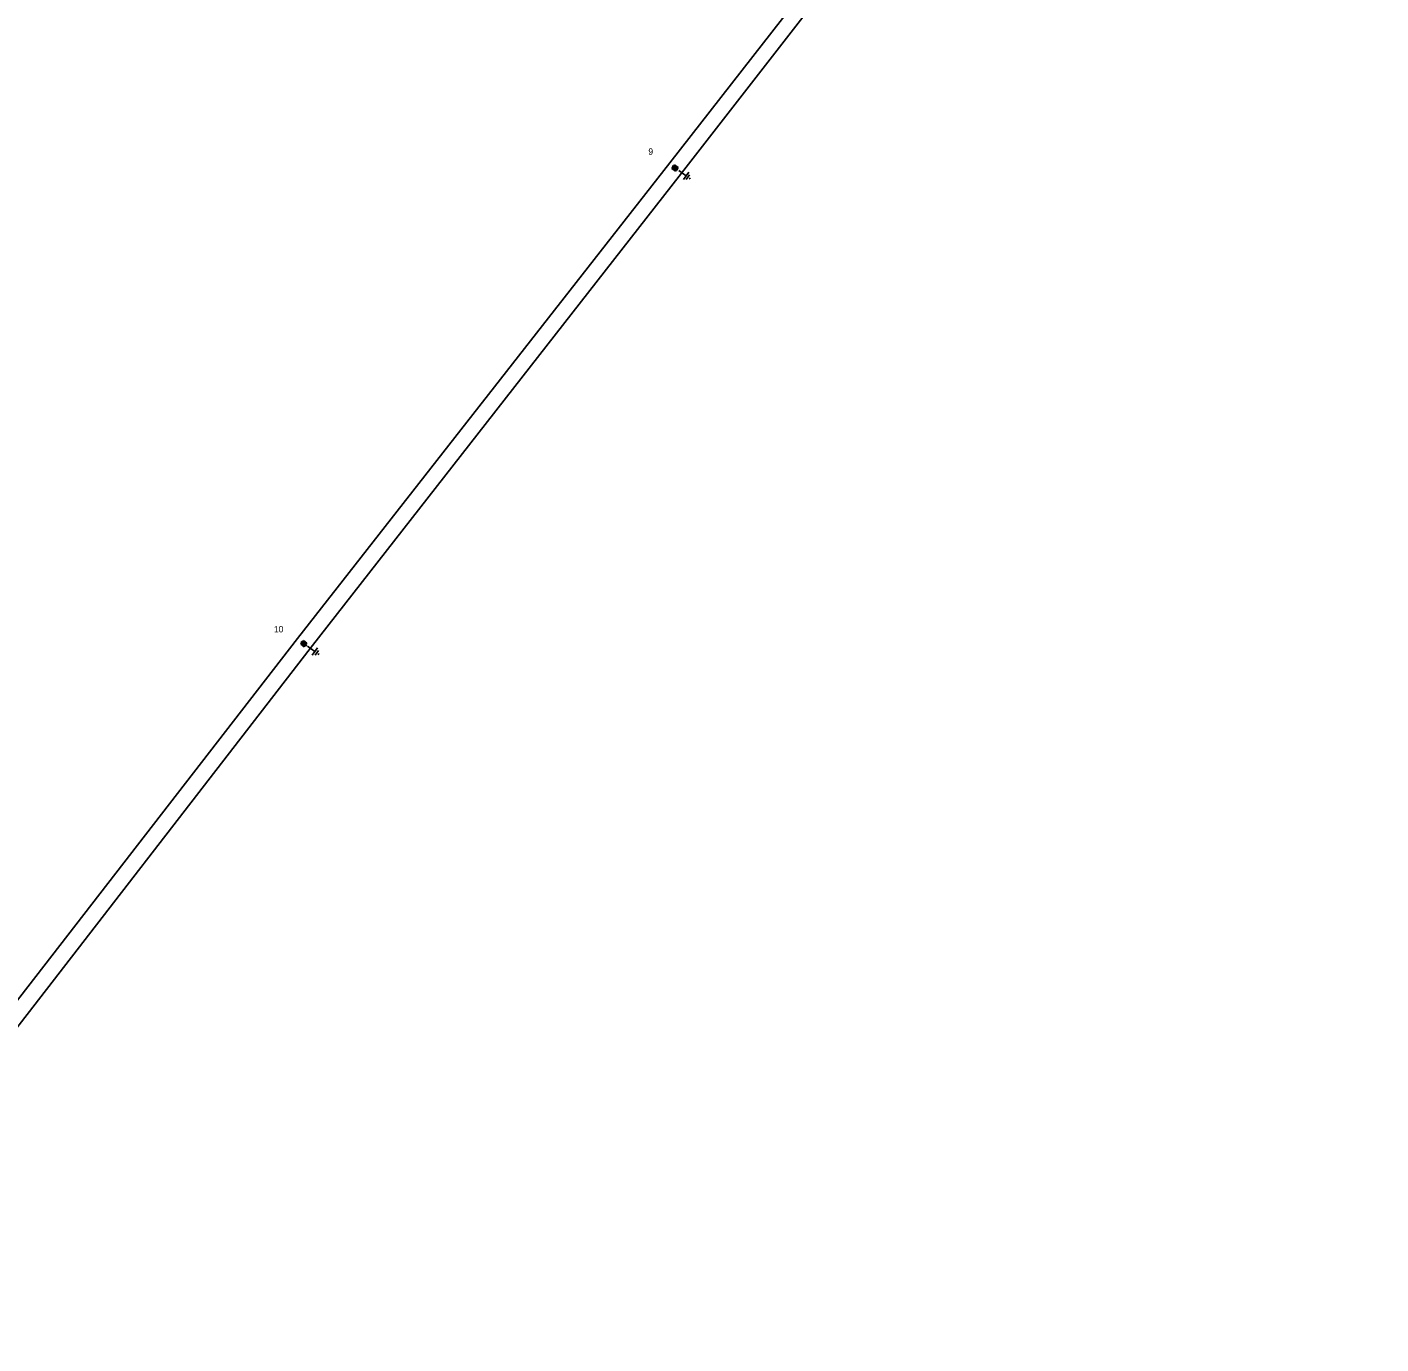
# Model space of a CAD drawing. Extents: x -788491 to -785797, y -1154753 to -1152002.
# Drawn here: x -787571.6 to -787198.5, y -1154725.3 to -1154362.4 of the extents above; entities that cross this region are included whole.
import ezdxf

# ---------------------------------------------------------------- set-up
doc = ezdxf.new("R2010")
doc.units = 0
for name, color, linetype in [('Vrstva 1', 7, 'Continuous'), ('Vrstva 13', 7, 'Continuous'), ('Vrstva 14', 7, 'Continuous'), ('Vrstva 15', 7, 'Continuous'), ('Vrstva 2', 7, 'Continuous')]:
    doc.layers.add(name, color=color, linetype=linetype)

# ---------------------------------------------------------------- blocks, each defined once
blk = doc.blocks.new('VN810')
at = {"layer": 'Vrstva 14'}
for points in [[(0, -1.25), (0, -3.75)], [(1.25, -3.75), (-1.25, -3.75)], [(0.77, -4.37), (-0.8, -4.37)], [(0, -5), (-0.25, -5)], [(0.27, -5), (0, -5)]]:
    blk.add_lwpolyline(points, dxfattribs=at)
blk = doc.blocks.new('VN470')
at = {"layer": 'Vrstva 2'}
for points in [[(-1.23, 1.22), (1.23, 1.22)], [(-1.23, -1.23), (-1.23, 1.22)], [(-0.92, 0.9), (0.92, 0.9)], [(-0.92, -0.95), (-0.92, 0.9)], [(-0.61, 0.61), (0.61, 0.61)], [(-0.61, -0.62), (-0.61, 0.61)], [(-0.31, -0.27), (-0.31, 0.34)], [(-0.31, 0.34), (0.31, 0.34)], [(0, 1.22), (0, 1.97)], [(0.31, 0.34), (0.31, -0.27)], [(0.61, 0.61), (0.61, -0.62)], [(0.92, 0.9), (0.92, -0.95)], [(1.23, 1.22), (1.23, -1.23)], [(1.23, -1.23), (-1.23, -1.23)], [(0.92, -0.95), (-0.92, -0.95)], [(0.61, -0.62), (-0.61, -0.62)], [(0.31, -0.27), (-0.31, -0.27)], [(0, -1.23), (0, -1.98)]]:
    blk.add_lwpolyline(points, dxfattribs=at)

msp = doc.modelspace()

# ---------------------------------------------------------------- linework, layer by layer
at = {"layer": 'Vrstva 1'}
for points in [[(-787642.19, -1154725.26), (-787585.43, -1154652.32), (-787493.57, -1154533.63), (-787391.24, -1154402.66), (-787292.22, -1154275.24), (-787198.47, -1154154.71), (-787293.67, -1153999.52)], [(-787647.19, -1154724.52), (-787589.09, -1154649.65), (-787497.04, -1154530.83), (-787394.48, -1154399.84), (-787295.42, -1154272.85), (-787202.42, -1154153.82), (-787297.28, -1154001.71)]]:
    msp.add_lwpolyline(points, dxfattribs=at)

# ---------------------------------------------------------------- block references
at = {"layer": 'Vrstva 13', "xscale": 0.5000000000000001, "yscale": 0.5000000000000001, "rotation": 53.1701388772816}
for p in [(-787393.02, -1154401.19), (-787495.31, -1154532.3)]:
    msp.add_blockref('VN470', p, dxfattribs=at)
at = {"layer": 'Vrstva 15'}
for p, rotation in [((-787393.02, -1154401.19), 54.338363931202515), ((-787495.31, -1154532.3), 54.31813056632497)]:
    msp.add_blockref('VN810', p, dxfattribs=dict(at, rotation=rotation))

# ---------------------------------------------------------------- texts
at = {"layer": 'Vrstva 14'}
for s, p in [('9', (-787400.36, -1154397.57)), ('10', (-787503.56, -1154529.2))]:
    msp.add_text(s, height=1.75, dxfattribs=at).set_placement(p)

doc.saveas('drawing.dxf')
